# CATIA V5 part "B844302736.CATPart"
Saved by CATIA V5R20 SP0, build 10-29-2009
Part number: B844302736
Revision: 2
Definition: design
Nomenclature: B844302736
Source: made
Description: NOT SPECIFIED
Bounding box of the stored display mesh (mm): x -24.5 to 24.5, y -24.5 to 24.5, z -27 to 36
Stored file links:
  C:\Users\Utente\Desktop\3D files B844\B844302736.CATPart
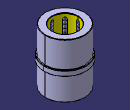
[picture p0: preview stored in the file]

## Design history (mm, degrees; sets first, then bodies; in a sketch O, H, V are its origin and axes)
Body1 "MANIFOLD_SOLID_BREP #38" (main body)
  Solid1: solid without history
Body2 "MANIFOLD_SOLID_BREP #76"
  Solid2: solid without history
Body3 "MANIFOLD_SOLID_BREP #114"
  Solid3: solid without history
Body4 "MANIFOLD_SOLID_BREP #152"
  Solid4: solid without history
Body5 "MANIFOLD_SOLID_BREP #190"
  Solid5: solid without history
Body6 "MANIFOLD_SOLID_BREP #228"
  Solid6: solid without history
Body7 "MANIFOLD_SOLID_BREP #266"
  Solid7: solid without history
Body8 "MANIFOLD_SOLID_BREP #304"
  Solid8: solid without history
Body9 "MANIFOLD_SOLID_BREP #2400"
  Solid9: solid without history
Body10 "MANIFOLD_SOLID_BREP #2438"
  Solid10: solid without history
Body11 "MANIFOLD_SOLID_BREP #2476"
  Solid11: solid without history
Body12 "MANIFOLD_SOLID_BREP #2514"
  Solid12: solid without history
Body13 "MANIFOLD_SOLID_BREP #2552"
  Solid13: solid without history
Body14 "MANIFOLD_SOLID_BREP #2590"
  Solid14: solid without history
Body15 "MANIFOLD_SOLID_BREP #2628"
  Solid15: solid without history
Body16 "MANIFOLD_SOLID_BREP #2666"
  Solid16: solid without history
Body17 "MANIFOLD_SOLID_BREP #2704"
  Solid17: solid without history
Body18 "MANIFOLD_SOLID_BREP #2742"
  Solid18: solid without history
Body19 "MANIFOLD_SOLID_BREP #2780"
  Solid19: solid without history
Body20 "MANIFOLD_SOLID_BREP #2818"
  Solid20: solid without history
Body21 "MANIFOLD_SOLID_BREP #2856"
  Solid21: solid without history
Body22 "MANIFOLD_SOLID_BREP #2894"
  Solid22: solid without history
Body23 "MANIFOLD_SOLID_BREP #2932"
  Solid23: solid without history
Body24 "MANIFOLD_SOLID_BREP #2970"
  Solid24: solid without history
Body25 "MANIFOLD_SOLID_BREP #3008"
  Solid25: solid without history
Body26 "MANIFOLD_SOLID_BREP #3046"
  Solid26: solid without history
Body27 "MANIFOLD_SOLID_BREP #3084"
  Solid27: solid without history
Body28 "MANIFOLD_SOLID_BREP #3122"
  Solid28: solid without history
Body29 "MANIFOLD_SOLID_BREP #3160"
  Solid29: solid without history
Body30 "MANIFOLD_SOLID_BREP #3198"
  Solid30: solid without history
Body31 "MANIFOLD_SOLID_BREP #3236"
  Solid31: solid without history
Body32 "MANIFOLD_SOLID_BREP #3274"
  Solid32: solid without history
Body33 "MANIFOLD_SOLID_BREP #3312"
  Solid33: solid without history
Body34 "MANIFOLD_SOLID_BREP #3350"
  Solid34: solid without history
Body35 "MANIFOLD_SOLID_BREP #3388"
  Solid35: solid without history
Body36 "MANIFOLD_SOLID_BREP #3426"
  Solid36: solid without history
Body37 "MANIFOLD_SOLID_BREP #3464"
  Solid37: solid without history
Body38 "MANIFOLD_SOLID_BREP #3502"
  Solid38: solid without history
Body39 "MANIFOLD_SOLID_BREP #3540"
  Solid39: solid without history
Body40 "MANIFOLD_SOLID_BREP #3578"
  Solid40: solid without history
Body41 "MANIFOLD_SOLID_BREP #3616"
  Solid41: solid without history
Body42 "MANIFOLD_SOLID_BREP #3654"
  Solid42: solid without history
Body43 "MANIFOLD_SOLID_BREP #3692"
  Solid43: solid without history
Body44 "MANIFOLD_SOLID_BREP #3730"
  Solid44: solid without history
Body45 "MANIFOLD_SOLID_BREP #3768"
  Solid45: solid without history
Body46 "MANIFOLD_SOLID_BREP #3806"
  Solid46: solid without history
Body47 "MANIFOLD_SOLID_BREP #3844"
  Solid47: solid without history
Body48 "MANIFOLD_SOLID_BREP #3882"
  Solid48: solid without history
Body49 "MANIFOLD_SOLID_BREP #3920"
  Solid49: solid without history
Body50 "MANIFOLD_SOLID_BREP #3958"
  Solid50: solid without history
Body51 "MANIFOLD_SOLID_BREP #3996"
  Solid51: solid without history
Body52 "MANIFOLD_SOLID_BREP #4034"
  Solid52: solid without history
Body53 "MANIFOLD_SOLID_BREP #4072"
  Solid53: solid without history
Body54 "MANIFOLD_SOLID_BREP #4110"
  Solid54: solid without history
Body55 "MANIFOLD_SOLID_BREP #4148"
  Solid55: solid without history
Body56 "MANIFOLD_SOLID_BREP #4186"
  Solid56: solid without history
Body57 "MANIFOLD_SOLID_BREP #4224"
  Solid57: solid without history
Body58 "MANIFOLD_SOLID_BREP #4262"
  Solid58: solid without history
Body59 "MANIFOLD_SOLID_BREP #4300"
  Solid59: solid without history
Body60 "MANIFOLD_SOLID_BREP #4338"
  Solid60: solid without history
Body61 "MANIFOLD_SOLID_BREP #4376"
  Solid61: solid without history
Body62 "MANIFOLD_SOLID_BREP #4414"
  Solid62: solid without history
Body63 "MANIFOLD_SOLID_BREP #4452"
  Solid63: solid without history
Body64 "MANIFOLD_SOLID_BREP #4490"
  Solid64: solid without history
Body65 "MANIFOLD_SOLID_BREP #4528"
  Solid65: solid without history
Body66 "MANIFOLD_SOLID_BREP #4566"
  Solid66: solid without history
Body67 "MANIFOLD_SOLID_BREP #4604"
  Solid67: solid without history
Body68 "MANIFOLD_SOLID_BREP #4642"
  Solid68: solid without history
Body69 "MANIFOLD_SOLID_BREP #4680"
  Solid69: solid without history
Body70 "MANIFOLD_SOLID_BREP #4718"
  Solid70: solid without history
Body71 "MANIFOLD_SOLID_BREP #4756"
  Solid71: solid without history
Body72 "MANIFOLD_SOLID_BREP #4794"
  Solid72: solid without history
Body73 "MANIFOLD_SOLID_BREP #4832"
  Solid73: solid without history
Body74 "MANIFOLD_SOLID_BREP #4870"
  Solid74: solid without history
Body75 "MANIFOLD_SOLID_BREP #4908"
  Solid75: solid without history
Body76 "MANIFOLD_SOLID_BREP #4946"
  Solid76: solid without history
Body77 "MANIFOLD_SOLID_BREP #4984"
  Solid77: solid without history
Body78 "MANIFOLD_SOLID_BREP #5022"
  Solid78: solid without history
Body79 "MANIFOLD_SOLID_BREP #5060"
  Solid79: solid without history
Body80 "MANIFOLD_SOLID_BREP #5098"
  Solid80: solid without history
Body81 "MANIFOLD_SOLID_BREP #5136"
  Solid81: solid without history
Body82 "MANIFOLD_SOLID_BREP #5174"
  Solid82: solid without history
Body83 "MANIFOLD_SOLID_BREP #5212"
  Solid83: solid without history
Body84 "MANIFOLD_SOLID_BREP #5250"
  Solid84: solid without history
Body85 "MANIFOLD_SOLID_BREP #5288"
  Solid85: solid without history
Body86 "MANIFOLD_SOLID_BREP #5326"
  Solid86: solid without history
Body87 "MANIFOLD_SOLID_BREP #5364"
  Solid87: solid without history
Body88 "MANIFOLD_SOLID_BREP #5402"
  Solid88: solid without history
Body89 "MANIFOLD_SOLID_BREP #5440"
  Solid89: solid without history
Body90 "MANIFOLD_SOLID_BREP #5478"
  Solid90: solid without history
Body91 "MANIFOLD_SOLID_BREP #5516"
  Solid91: solid without history
Body92 "MANIFOLD_SOLID_BREP #5554"
  Solid92: solid without history
Body93 "MANIFOLD_SOLID_BREP #5592"
  Solid93: solid without history
Body94 "MANIFOLD_SOLID_BREP #5630"
  Solid94: solid without history
Body95 "MANIFOLD_SOLID_BREP #5668"
  Solid95: solid without history
Body96 "MANIFOLD_SOLID_BREP #5706"
  Solid96: solid without history
Body97 "MANIFOLD_SOLID_BREP #5744"
  Solid97: solid without history
Body98 "MANIFOLD_SOLID_BREP #5782"
  Solid98: solid without history
Body99 "MANIFOLD_SOLID_BREP #5820"
  Solid99: solid without history
Body100 "MANIFOLD_SOLID_BREP #5858"
  Solid100: solid without history
Body101 "MANIFOLD_SOLID_BREP #5896"
  Solid101: solid without history
Body102 "MANIFOLD_SOLID_BREP #5934"
  Solid102: solid without history
Body103 "MANIFOLD_SOLID_BREP #5972"
  Solid103: solid without history
Body104 "MANIFOLD_SOLID_BREP #6010"
  Solid104: solid without history
Body105 "MANIFOLD_SOLID_BREP #6048"
  Solid105: solid without history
